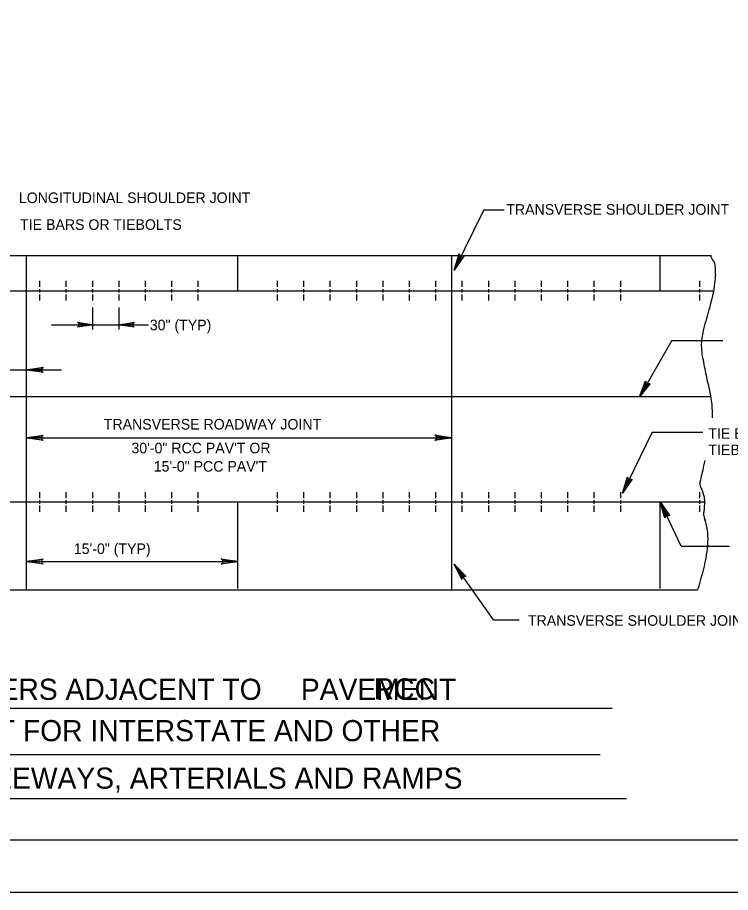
# Model space of a CAD drawing. Extents: x 638216 to 639962, y 297510 to 299292.
# Drawn here: x 638406.9 to 638609.5, y 297510.2 to 297758.8 of the extents above; entities that cross this region are included whole.
import ezdxf

# ---------------------------------------------------------------- set-up
doc = ezdxf.new("R2010")
doc.units = 0
for name, color, linetype in [('1', 7, 'Continuous'), ('2', 7, 'Continuous'), ('3', 7, 'Continuous'), ('PLT-BNDY', 7, 'Continuous')]:
    doc.layers.add(name, color=color, linetype=linetype)

msp = doc.modelspace()

# ---------------------------------------------------------------- linework, layer by layer
at = {"layer": '1'}
msp.add_lwpolyline([(639041.88, 297525.24), (639041.88, 298089.24), (638255.88, 298089.24), (638255.88, 297525.24), (639041.88, 297525.24), (639041.88, 297551.6), (638841.88, 297551.6), (638841.88, 297616.28), (639041.88, 297616.28), (639041.88, 297645.24), (638841.88, 297645.24), (638841.88, 297525.24), (638920.69, 297525.24), (638920.69, 297551.6), (638920.69, 297525.24), (638997.69, 297525.24), (638997.69, 297551.6), (638997.69, 297539.28), (639041.88, 297539.28)], dxfattribs=at)
msp.add_lwpolyline([(639041.88, 297525.24), (639041.88, 298089.24), (638255.88, 298089.24), (638255.88, 297525.24), (639041.88, 297525.24), (639041.88, 297551.6), (638841.88, 297551.6), (638841.88, 297616.28), (639041.88, 297616.28), (639041.88, 297645.24), (638841.88, 297645.24), (638841.88, 297525.24), (638920.69, 297525.24), (638920.69, 297551.6), (638920.69, 297525.24), (638997.69, 297525.24), (638997.69, 297551.6), (638997.69, 297539.28), (639041.88, 297539.28)], dxfattribs=at)
msp.add_lwpolyline([(639041.88, 297525.24), (639041.88, 298089.24), (638255.88, 298089.24), (638255.88, 297525.24), (639041.88, 297525.24), (639041.88, 297551.6), (638841.88, 297551.6), (638841.88, 297616.28), (639041.88, 297616.28), (639041.88, 297645.24), (638841.88, 297645.24), (638841.88, 297525.24), (638920.69, 297525.24), (638920.69, 297551.6), (638920.69, 297525.24), (638997.69, 297525.24), (638997.69, 297551.6), (638997.69, 297539.28), (639041.88, 297539.28)], dxfattribs=at)
at = {"layer": '2'}
for p, q in [((638539.37, 297704.2), (638530.98, 297687.02)), ((638539.37, 297704.2), (638545.18, 297704.2)), ((638270.14, 297691.19), (638603.98, 297691.19)), ((638409.46, 297596.19), (638409.46, 297691.19)), ((638469.5, 297681.19), (638469.5, 297691.19)), ((638530.28, 297596.19), (638530.28, 297691.19)), ((638589.48, 297681.19), (638589.48, 297691.19)), ((638413.28, 297682.3), (638413.28, 297684)), ((638420.78, 297682.3), (638420.78, 297684)), ((638428.28, 297682.3), (638428.28, 297684)), ((638435.78, 297682.3), (638435.78, 297684)), ((638443.28, 297682.3), (638443.28, 297684)), ((638450.78, 297682.3), (638450.78, 297684)), ((638458.28, 297682.3), (638458.28, 297684)), ((638458.28, 297682.3), (638458.28, 297684)), ((638480.78, 297682.3), (638480.78, 297684)), ((638488.28, 297682.3), (638488.28, 297684)), ((638488.28, 297682.3), (638488.28, 297684)), ((638495.78, 297682.3), (638495.78, 297684)), ((638495.78, 297682.3), (638495.78, 297684)), ((638503.28, 297682.3), (638503.28, 297684)), ((638503.28, 297682.3), (638503.28, 297684)), ((638510.78, 297682.3), (638510.78, 297684)), ((638518.28, 297682.3), (638518.28, 297684)), ((638525.78, 297682.3), (638525.78, 297684)), ((638533.28, 297682.3), (638533.28, 297684)), ((638540.78, 297682.3), (638540.78, 297684)), ((638548.28, 297682.3), (638548.28, 297684)), ((638555.78, 297682.3), (638555.78, 297684)), ((638563.28, 297682.3), (638563.28, 297684)), ((638570.78, 297682.3), (638570.78, 297684)), ((638578.28, 297682.3), (638578.28, 297684)), ((638600.78, 297682.3), (638600.78, 297684)), ((638270.23, 297681.19), (638604.59, 297681.19)), ((638413.28, 297680.69), (638413.28, 297681.66)), ((638420.78, 297680.69), (638420.78, 297681.66)), ((638428.28, 297680.69), (638428.28, 297681.66)), ((638435.78, 297680.69), (638435.78, 297681.66)), ((638443.28, 297680.69), (638443.28, 297681.66)), ((638450.78, 297680.69), (638450.78, 297681.66)), ((638458.28, 297680.69), (638458.28, 297681.66)), ((638458.28, 297680.69), (638458.28, 297681.66)), ((638480.78, 297680.69), (638480.78, 297681.66)), ((638488.28, 297680.69), (638488.28, 297681.66)), ((638488.28, 297680.69), (638488.28, 297681.66)), ((638495.78, 297680.69), (638495.78, 297681.66)), ((638495.78, 297680.69), (638495.78, 297681.66)), ((638503.28, 297680.69), (638503.28, 297681.66)), ((638503.28, 297680.69), (638503.28, 297681.66)), ((638510.78, 297680.69), (638510.78, 297681.66)), ((638518.28, 297680.69), (638518.28, 297681.66)), ((638525.78, 297680.69), (638525.78, 297681.66)), ((638533.28, 297680.69), (638533.28, 297681.66)), ((638540.78, 297680.69), (638540.78, 297681.66)), ((638548.28, 297680.69), (638548.28, 297681.66)), ((638555.78, 297680.69), (638555.78, 297681.66)), ((638563.28, 297680.69), (638563.28, 297681.66)), ((638570.78, 297680.69), (638570.78, 297681.66)), ((638578.28, 297680.69), (638578.28, 297681.66)), ((638600.78, 297680.69), (638600.78, 297681.66)), ((638413.28, 297678.38), (638413.28, 297680.15)), ((638420.78, 297678.38), (638420.78, 297680.15)), ((638428.28, 297678.38), (638428.28, 297680.15)), ((638435.78, 297678.38), (638435.78, 297680.15)), ((638443.28, 297678.38), (638443.28, 297680.15)), ((638450.78, 297678.38), (638450.78, 297680.15)), ((638458.28, 297678.38), (638458.28, 297680.15)), ((638458.28, 297678.38), (638458.28, 297680.15)), ((638480.78, 297678.38), (638480.78, 297680.15)), ((638488.28, 297678.38), (638488.28, 297680.15)), ((638495.78, 297678.38), (638495.78, 297680.15)), ((638503.28, 297678.38), (638503.28, 297680.15)), ((638510.78, 297678.38), (638510.78, 297680.15)), ((638518.28, 297678.38), (638518.28, 297680.15)), ((638525.78, 297678.38), (638525.78, 297680.15)), ((638533.28, 297678.38), (638533.28, 297680.15)), ((638540.78, 297678.38), (638540.78, 297680.15)), ((638548.28, 297678.38), (638548.28, 297680.15)), ((638555.78, 297678.38), (638555.78, 297680.15)), ((638563.28, 297678.38), (638563.28, 297680.15)), ((638570.78, 297678.38), (638570.78, 297680.15)), ((638578.28, 297678.38), (638578.28, 297680.15)), ((638600.78, 297678.38), (638600.78, 297680.15)), ((638428.28, 297670.2), (638428.28, 297676.44)), ((638435.78, 297670.2), (638435.78, 297676.44)), ((638416.6, 297671.54), (638435.78, 297671.54)), ((638435.78, 297671.54), (638444.09, 297671.54)), ((638592.84, 297667.1), (638583.64, 297651.1)), ((638592.84, 297667.1), (638607.27, 297667.1)), ((638383.1, 297658.7), (638409.46, 297658.7)), ((638409.46, 297658.7), (638419.4, 297658.7)), ((638308.85, 297651.19), (638603.68, 297651.19)), ((638587.17, 297641.06), (638578.81, 297623.7)), ((638587.17, 297641.06), (638601.6, 297641.06)), ((638409.46, 297639.45), (638530.28, 297639.45)), ((638413.28, 297622.3), (638413.28, 297624)), ((638420.78, 297622.3), (638420.78, 297624)), ((638428.28, 297622.3), (638428.28, 297624)), ((638435.78, 297622.3), (638435.78, 297624)), ((638443.28, 297622.3), (638443.28, 297624)), ((638450.78, 297622.3), (638450.78, 297624)), ((638458.28, 297622.3), (638458.28, 297624)), ((638480.78, 297622.3), (638480.78, 297624)), ((638488.28, 297622.3), (638488.28, 297624)), ((638495.78, 297622.3), (638495.78, 297624)), ((638503.28, 297622.3), (638503.28, 297624)), ((638510.78, 297622.3), (638510.78, 297624)), ((638518.28, 297622.3), (638518.28, 297624)), ((638525.78, 297622.3), (638525.78, 297624)), ((638533.28, 297622.3), (638533.28, 297624)), ((638540.78, 297622.3), (638540.78, 297624)), ((638548.28, 297622.3), (638548.28, 297624)), ((638555.78, 297622.3), (638555.78, 297624)), ((638563.28, 297622.3), (638563.28, 297624)), ((638570.78, 297622.3), (638570.78, 297624)), ((638578.28, 297622.3), (638578.28, 297624)), ((638600.78, 297622.3), (638600.78, 297624)), ((638262.88, 297621.19), (638602.13, 297621.19)), ((638413.28, 297620.69), (638413.28, 297621.66)), ((638420.78, 297620.69), (638420.78, 297621.66)), ((638428.28, 297620.69), (638428.28, 297621.66)), ((638428.28, 297620.69), (638428.28, 297621.66)), ((638435.78, 297620.69), (638435.78, 297621.66)), ((638443.28, 297620.69), (638443.28, 297621.66)), ((638450.78, 297620.69), (638450.78, 297621.66)), ((638458.28, 297620.69), (638458.28, 297621.66)), ((638469.5, 297596.58), (638469.5, 297621.19)), ((638480.78, 297620.69), (638480.78, 297621.66)), ((638488.28, 297620.69), (638488.28, 297621.66)), ((638495.78, 297620.69), (638495.78, 297621.66)), ((638503.28, 297620.69), (638503.28, 297621.66)), ((638510.78, 297620.69), (638510.78, 297621.66)), ((638518.25, 297620.68), (638518.25, 297621.65)), ((638518.28, 297620.69), (638518.28, 297621.66)), ((638518.28, 297620.69), (638518.28, 297621.66)), ((638525.77, 297620.76), (638525.77, 297621.73)), ((638525.78, 297620.69), (638525.78, 297621.66)), ((638525.78, 297620.69), (638525.78, 297621.66)), ((638533.28, 297620.69), (638533.28, 297621.66)), ((638533.28, 297620.69), (638533.28, 297621.66)), ((638540.78, 297620.69), (638540.78, 297621.66)), ((638548.28, 297620.69), (638548.28, 297621.66)), ((638555.78, 297620.69), (638555.78, 297621.66)), ((638563.28, 297620.69), (638563.28, 297621.66)), ((638570.78, 297620.69), (638570.78, 297621.66)), ((638578.28, 297620.69), (638578.28, 297621.66)), ((638595.44, 297608.67), (638589.48, 297621.19)), ((638589.48, 297596.58), (638589.48, 297621.19)), ((638600.78, 297620.69), (638600.78, 297621.66)), ((638413.28, 297618.38), (638413.28, 297620.15)), ((638420.78, 297618.38), (638420.78, 297620.15)), ((638428.28, 297618.38), (638428.28, 297620.15)), ((638428.28, 297618.38), (638428.28, 297620.15)), ((638435.78, 297618.38), (638435.78, 297620.15)), ((638443.28, 297618.38), (638443.28, 297620.15)), ((638450.78, 297618.38), (638450.78, 297620.15)), ((638458.28, 297618.38), (638458.28, 297620.15)), ((638480.78, 297618.38), (638480.78, 297620.15)), ((638488.28, 297618.38), (638488.28, 297620.15)), ((638495.78, 297618.38), (638495.78, 297620.15)), ((638503.28, 297618.38), (638503.28, 297620.15)), ((638510.78, 297618.38), (638510.78, 297620.15)), ((638518.25, 297618.37), (638518.25, 297620.14)), ((638518.28, 297618.38), (638518.28, 297620.15)), ((638518.28, 297618.38), (638518.28, 297620.15)), ((638525.77, 297618.45), (638525.77, 297620.22)), ((638525.78, 297618.38), (638525.78, 297620.15)), ((638525.78, 297618.38), (638525.78, 297620.15)), ((638533.28, 297618.38), (638533.28, 297620.15)), ((638533.28, 297618.38), (638533.28, 297620.15)), ((638540.78, 297618.38), (638540.78, 297620.15)), ((638548.28, 297618.38), (638548.28, 297620.15)), ((638555.78, 297618.38), (638555.78, 297620.15)), ((638563.28, 297618.38), (638563.28, 297620.15)), ((638570.78, 297618.38), (638570.78, 297620.15)), ((638578.28, 297618.38), (638578.28, 297620.15)), ((638600.78, 297618.38), (638600.78, 297620.15)), ((638595.44, 297608.67), (638609.16, 297608.67)), ((638409.46, 297604.29), (638469.59, 297604.29)), ((638542.19, 297587.71), (638530.98, 297603.5)), ((638266.73, 297596.19), (638600.13, 297596.19)), ((638542.19, 297587.71), (638549.4, 297587.71)), ((638320.26, 297562.64), (638575.86, 297562.64)), ((638321.73, 297549.46), (638572.46, 297549.46)), ((638319.33, 297536.91), (638579.89, 297536.91))]:
    msp.add_line(p, q, dxfattribs=at)
for points in [[(638533.48, 297690.85), (638533.11, 297690.84), (638530.98, 297687.02), (638533.48, 297690.85), (638533.76, 297690.97), (638530.98, 297687.02), (638532.7, 297691.04), (638532.48, 297691.33), (638530.98, 297687.02), (638532.39, 297691.64), (638532.48, 297691.33)], [(638424.18, 297672.04), (638424.34, 297671.75), (638428.27, 297671.53), (638424.18, 297672.04), (638423.97, 297672.22), (638428.27, 297671.53), (638424.34, 297671.34), (638424.19, 297671.04), (638428.27, 297671.53), (638423.97, 297670.85), (638424.19, 297671.04)], [(638439.87, 297671.02), (638439.71, 297671.32), (638435.78, 297671.53), (638439.87, 297671.02), (638440.07, 297670.84), (638435.78, 297671.53), (638439.71, 297671.73), (638439.85, 297672.02), (638435.78, 297671.53), (638440.07, 297672.22), (638439.85, 297672.02)], [(638414, 297658.13), (638413.83, 297658.46), (638409.46, 297658.7), (638414, 297658.13), (638414.24, 297657.93), (638409.46, 297658.7), (638413.83, 297658.92), (638413.99, 297659.24), (638409.46, 297658.7), (638414.24, 297659.46), (638413.99, 297659.24)], [(638586.4, 297654.75), (638586.03, 297654.77), (638583.64, 297651.1), (638586.4, 297654.75), (638586.69, 297654.86), (638583.64, 297651.1), (638585.63, 297655), (638585.43, 297655.3), (638583.64, 297651.1), (638585.36, 297655.62), (638585.43, 297655.3)], [(638414, 297638.88), (638413.83, 297639.21), (638409.46, 297639.45), (638414, 297638.88), (638414.23, 297638.68), (638409.46, 297639.45), (638413.83, 297639.67), (638413.99, 297639.99), (638409.46, 297639.45), (638414.23, 297640.21), (638413.99, 297639.99)], [(638525.73, 297640.02), (638525.9, 297639.69), (638530.28, 297639.45), (638525.73, 297640.02), (638525.5, 297640.22), (638530.28, 297639.45), (638525.91, 297639.24), (638525.75, 297638.91), (638530.28, 297639.45), (638525.5, 297638.69), (638525.75, 297638.91)], [(638581.3, 297627.54), (638580.93, 297627.53), (638578.81, 297623.7), (638581.3, 297627.54), (638581.58, 297627.67), (638578.81, 297623.7), (638580.51, 297627.73), (638580.29, 297628.01), (638578.81, 297623.7), (638580.2, 297628.33), (638580.29, 297628.01)], [(638590.92, 297616.85), (638591.14, 297617.14), (638589.48, 297621.19), (638590.92, 297616.85), (638590.84, 297616.55), (638589.48, 297621.19), (638591.55, 297617.34), (638591.92, 297617.34), (638589.48, 297621.19), (638592.22, 297617.21), (638591.92, 297617.34)], [(638414, 297603.72), (638413.83, 297604.05), (638409.46, 297604.29), (638414, 297603.72), (638414.23, 297603.52), (638409.46, 297604.29), (638413.83, 297604.5), (638413.99, 297604.83), (638409.46, 297604.29), (638414.23, 297605.05), (638413.99, 297604.83)], [(638465.05, 297604.86), (638465.22, 297604.53), (638469.59, 297604.29), (638465.05, 297604.86), (638464.82, 297605.06), (638469.59, 297604.29), (638465.22, 297604.07), (638465.06, 297603.75), (638469.59, 297604.29), (638464.82, 297603.53), (638465.06, 297603.75)], [(638533.14, 297599.47), (638533.31, 297599.8), (638530.98, 297603.5), (638533.14, 297599.47), (638533.11, 297599.17), (638530.98, 297603.5), (638533.68, 297600.07), (638534.04, 297600.12), (638530.98, 297603.5), (638534.36, 297600.05), (638534.04, 297600.12)]]:
    msp.add_lwpolyline(points, dxfattribs=at)
for points in [[(638605.18, 297685.91), (638605.17, 297687.73), (638604.9, 297689.32), (638603.99, 297690.8), (638603.98, 297691.19)], [(638605.18, 297685.91), (638604.95, 297683.33), (638603.46, 297676.22), (638601.83, 297670.29), (638601.17, 297666.15), (638601.66, 297661.53), (638602.66, 297656.56), (638604.12, 297648.96), (638604.27, 297645.05)], [(638602.15, 297632.99), (638601.83, 297631.43), (638600.77, 297626.75)], [(638600.77, 297626.75), (638600.84, 297625.79), (638601.46, 297624.34), (638601.95, 297622.48), (638602.12, 297621.33), (638601.99, 297619.8), (638601.95, 297618.93), (638601.79, 297617.81), (638602.04, 297616.61), (638602.25, 297615.79)], [(638602, 297616.5), (638602.25, 297615.79), (638602.92, 297608.87), (638602.42, 297605.23), (638600.13, 297596.19)]]:
    msp.add_spline(points, degree=3, dxfattribs=at)
at = {"layer": 'PLT-BNDY'}
msp.add_lwpolyline([(638215.88, 298104.24), (639056.88, 298104.24), (639056.88, 297510.24), (638215.88, 297510.24)], close=True, dxfattribs=at)

# ---------------------------------------------------------------- texts
at = {"layer": '1'}
msp.add_text('15\'-0" (TYP)', height=3, dxfattribs=at).set_placement((638422.93, 297606.41))
at = {"layer": '3'}
for s, height, p in [('LONGITUDINAL SHOULDER JOINT', 3, (638407.32, 297706.11)), ('TRANSVERSE SHOULDER JOINT', 3, (638545.78, 297702.79)), ('TIE BARS OR TIEBOLTS', 3, (638407.67, 297698.49)), ('30" (TYP)', 3, (638444.51, 297669.96)), ('TRANSVERSE ROADWAY JOINT', 3, (638431.45, 297641.77)), ('TIE BARS OR', 3, (638603.19, 297639.13)), ('30\'-0" RCC PAV\'T OR', 3, (638439.29, 297635.01)), ('TIEBOLTS', 3, (638603.19, 297634.5)), ('15\'-0" PCC PAV\'T', 3, (638445.62, 297629.81)), ('TRANSVERSE SHOULDER JOINT', 3, (638551.93, 297586.01)), ('CONCRETE SHOULDERS ADJACENT TO     PAVEMENT', 6, (638321.14, 297564.97)), ('RCC', 6, (638508.12, 297565.08)), ('AND PCC PAVEMENT FOR INTERSTATE AND OTHER', 6, (638323.76, 297553.22)), ('LIMITED ACCESS FREEWAYS, ARTERIALS AND RAMPS', 6, (638320.22, 297539.73))]:
    msp.add_text(s, height=height, dxfattribs=at).set_placement(p)

doc.saveas('drawing.dxf')
